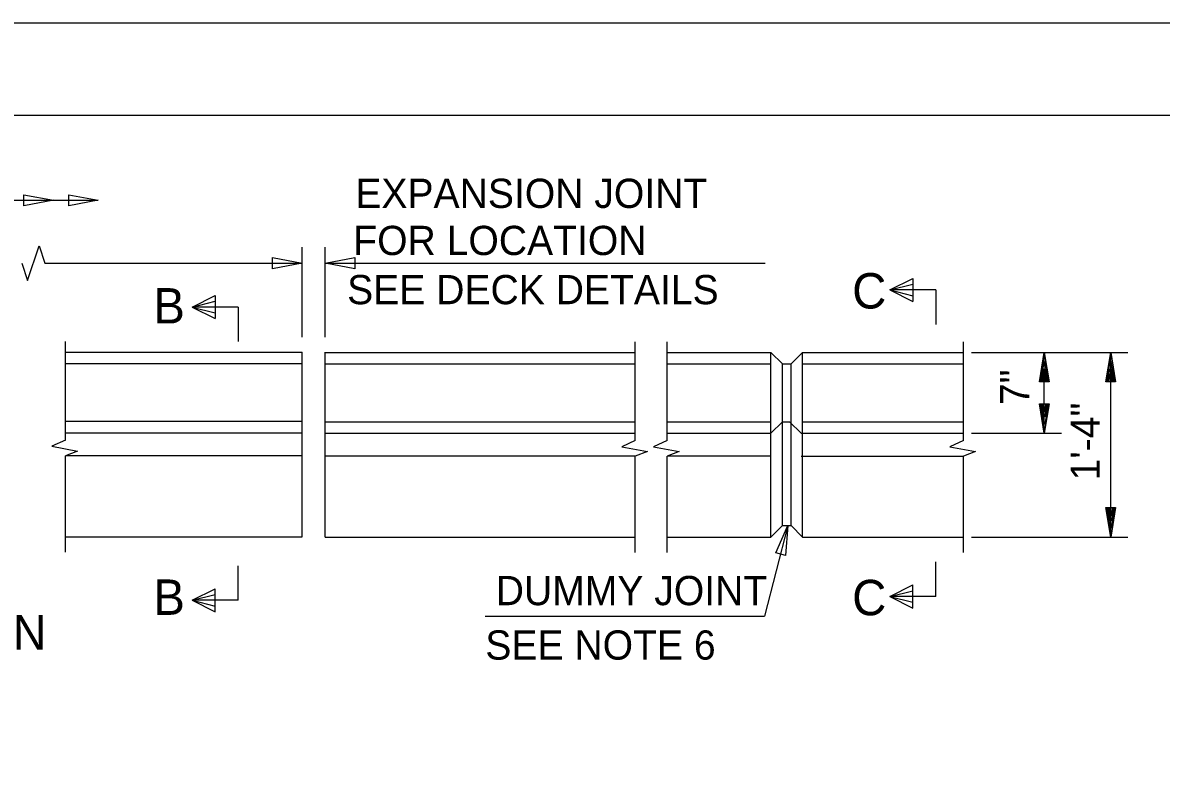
# Model space of a CAD drawing. Extents: x 0 to 34, y 0 to 23.5.
# Drawn here: x 9.78 to 15.94, y 17.93 to 22 of the extents above; entities that cross this region are included whole.
import ezdxf

# ---------------------------------------------------------------- set-up
doc = ezdxf.new("R2010")
doc.units = 0
for name, color, linetype in [('BORDER_ANNO_Cutsheet', 7, 'Continuous'), ('BRDG_ANNO_Anno-Sheet', 7, 'Continuous'), ('BRDG_ANNO_General-Notes', 7, 'Continuous'), ('BRDG_BASE_Obj-Line', 7, 'Continuous')]:
    doc.layers.add(name, color=color, linetype=linetype)

msp = doc.modelspace()

# ---------------------------------------------------------------- linework, layer by layer
at = {"layer": 'BORDER_ANNO_Cutsheet'}
msp.add_lwpolyline([(0, 22), (34, 22), (34, 0), (0, 0)], close=True, dxfattribs=at)
at = {"layer": 'BRDG_ANNO_Anno-Sheet'}
msp.add_lwpolyline([(1.5, 21.5), (33.5, 21.5), (33.5, 0.5), (1.5, 0.5)], close=True, dxfattribs=at)
at = {"layer": 'BRDG_ANNO_General-Notes'}
for p, q in [((2.9781, 21.0388), (10.1869, 21.0388)), ((9.7839, 21.0087), (9.7839, 21.0687)), ((9.7839, 21.0687), (9.9439, 21.0388)), ((9.9439, 21.0388), (9.7839, 21.0087)), ((10.0269, 21.0087), (10.0269, 21.0687)), ((10.0269, 21.0687), (10.1869, 21.0388)), ((10.1869, 21.0388), (10.0269, 21.0087)), ((11.2906, 20.2985), (11.2906, 20.7858)), ((11.4156, 20.2985), (11.4156, 20.7858)), ((11.1306, 20.6683), (11.1306, 20.7283)), ((11.1306, 20.7283), (11.2906, 20.6983)), ((11.4156, 20.6983), (11.5756, 20.7283)), ((11.5756, 20.7283), (11.5756, 20.6683)), ((9.8976, 20.6983), (11.2906, 20.6983)), ((11.2906, 20.6983), (11.1306, 20.6683)), ((11.4156, 20.6983), (13.798, 20.6983)), ((11.5756, 20.6683), (11.4156, 20.6983)), ((14.4728, 20.5532), (14.5978, 20.6157)), ((14.5978, 20.6157), (14.5978, 20.5532)), ((14.4728, 20.5532), (14.5978, 20.5844)), ((14.7228, 20.5532), (14.4728, 20.5532)), ((14.4728, 20.5532), (14.5978, 20.4907)), ((14.4728, 20.5532), (14.5978, 20.5219)), ((14.5978, 20.5532), (14.5978, 20.4907)), ((14.7228, 20.5532), (14.7228, 20.3657)), ((10.6951, 20.4609), (10.8201, 20.5234)), ((10.6951, 20.4609), (10.8201, 20.4921)), ((10.8201, 20.5234), (10.8201, 20.4609)), ((10.9451, 20.4609), (10.6951, 20.4609)), ((10.6951, 20.4609), (10.8201, 20.3984)), ((10.6951, 20.4609), (10.8201, 20.4296)), ((10.8201, 20.4609), (10.8201, 20.3984)), ((10.9451, 20.4609), (10.9451, 20.2734)), ((14.9156, 20.2151), (15.7633, 20.2151)), ((15.2889, 20.0595), (15.3065, 20.1665)), ((15.3098, 19.7776), (15.3098, 20.2151)), ((15.3307, 20.0595), (15.3131, 20.1665)), ((15.6486, 20.0595), (15.6662, 20.1665)), ((15.6696, 19.2151), (15.6696, 20.2151)), ((15.6905, 20.0595), (15.6729, 20.1665)), ((15.2948, 20.0595), (15.306, 20.1271)), ((15.3021, 20.0599), (15.3059, 20.0993)), ((15.3247, 20.0595), (15.3136, 20.1271)), ((15.3174, 20.0599), (15.3136, 20.0993)), ((15.6546, 20.0595), (15.6658, 20.1271)), ((15.6619, 20.0599), (15.6657, 20.0993)), ((15.6845, 20.0595), (15.6734, 20.1271)), ((15.6772, 20.0599), (15.6734, 20.0993)), ((15.2889, 19.9332), (15.3065, 19.8262)), ((15.2948, 19.9332), (15.306, 19.8656)), ((15.3021, 19.9328), (15.3059, 19.8934)), ((15.3307, 19.9332), (15.3131, 19.8262)), ((15.3247, 19.9332), (15.3136, 19.8656)), ((15.3174, 19.9328), (15.3136, 19.8934)), ((14.9156, 19.7776), (15.4035, 19.7776)), ((15.6486, 19.3707), (15.6662, 19.2637)), ((15.6546, 19.3707), (15.6658, 19.3031)), ((15.6619, 19.3703), (15.6657, 19.3309)), ((15.6905, 19.3707), (15.6729, 19.2637)), ((15.6845, 19.3707), (15.6734, 19.3031)), ((15.6772, 19.3703), (15.6734, 19.3309)), ((13.9222, 19.2776), (13.7952, 18.7874)), ((13.8563, 19.1294), (13.9222, 19.2776)), ((13.9222, 19.2776), (13.9079, 19.116)), ((14.9156, 19.2151), (15.7633, 19.2151)), ((13.9079, 19.116), (13.8563, 19.1294)), ((10.9451, 18.8728), (10.9451, 19.0603)), ((14.7228, 18.8935), (14.7228, 19.081)), ((10.6951, 18.8728), (10.8201, 18.9353)), ((10.8201, 18.8728), (10.8201, 18.9353)), ((14.4728, 18.8935), (14.5978, 18.956)), ((14.5978, 18.8935), (14.5978, 18.956)), ((10.6951, 18.8728), (10.8201, 18.9041)), ((10.9451, 18.8728), (10.6951, 18.8728)), ((10.6951, 18.8728), (10.8201, 18.8103)), ((10.6951, 18.8728), (10.8201, 18.8416)), ((10.8201, 18.8103), (10.8201, 18.8728)), ((14.4728, 18.8935), (14.5978, 18.9247)), ((14.7228, 18.8935), (14.4728, 18.8935)), ((14.4728, 18.8935), (14.5978, 18.831)), ((14.4728, 18.8935), (14.5978, 18.8622)), ((14.5978, 18.831), (14.5978, 18.8935)), ((12.2829, 18.7874), (13.7952, 18.7874))]:
    msp.add_line(p, q, dxfattribs=at)
msp.add_lwpolyline([(9.7726, 20.6983), (9.8039, 20.6046), (9.8664, 20.7921), (9.8976, 20.6983)], dxfattribs=at)
for points in [[(15.2834, 20.0551), (15.3098, 20.2151), (15.3362, 20.0551)], [(15.6432, 20.0551), (15.6696, 20.2151), (15.696, 20.0551)], [(15.3362, 19.9376), (15.3098, 19.7776), (15.2834, 19.9376)], [(15.696, 19.3751), (15.6696, 19.2151), (15.6432, 19.3751)]]:
    msp.add_lwpolyline(points, close=True, dxfattribs=at)
at = {"layer": 'BRDG_BASE_Obj-Line'}
for p, q in [((10.0093, 19.74), (10.0093, 20.2737)), ((13.0953, 19.738), (13.0953, 20.2718)), ((13.2671, 19.738), (13.2671, 20.2718)), ((14.8723, 19.738), (14.8723, 20.2718)), ((10.0093, 20.2171), (11.2906, 20.2171)), ((11.2906, 19.2171), (11.2906, 20.2171)), ((11.4156, 19.2151), (11.4156, 20.2171)), ((11.4156, 20.2151), (13.0953, 20.2151)), ((13.2671, 20.2151), (13.8296, 20.2151)), ((13.8296, 19.2151), (13.8296, 20.2151)), ((13.8921, 20.1526), (13.8296, 20.2151)), ((13.939, 20.1526), (14.0015, 20.2151)), ((14.0015, 20.2151), (14.8723, 20.2151)), ((14.0015, 19.2151), (14.0015, 20.2151)), ((10.0093, 20.1546), (11.2906, 20.1546)), ((11.4156, 20.1526), (13.0953, 20.1526)), ((13.2671, 20.1526), (13.8296, 20.1526)), ((13.8921, 19.2776), (13.8921, 20.1526)), ((13.8921, 20.1526), (13.939, 20.1526)), ((13.939, 19.2776), (13.939, 20.1526)), ((14.0015, 20.1526), (14.8723, 20.1526)), ((10.0093, 19.8421), (11.2906, 19.8421)), ((11.4156, 19.8401), (13.0953, 19.8401)), ((13.2671, 19.8401), (13.8296, 19.8401)), ((13.8296, 19.7776), (13.8921, 19.8401)), ((13.8921, 19.8401), (13.9312, 19.8401)), ((13.9937, 19.7776), (13.9312, 19.8401)), ((14.0015, 19.8401), (14.8723, 19.8401)), ((10.0093, 19.74), (9.9365, 19.7067)), ((10.0093, 19.7796), (11.2906, 19.7796)), ((11.4156, 19.7776), (13.0953, 19.7776)), ((13.0953, 19.738), (13.0224, 19.7047)), ((13.2671, 19.738), (13.1943, 19.7047)), ((13.2671, 19.7776), (13.8296, 19.7776)), ((13.9937, 19.7776), (14.8723, 19.7776)), ((14.8723, 19.738), (14.7995, 19.7047)), ((9.9365, 19.7067), (10.0745, 19.6808)), ((10.0745, 19.6808), (10.0093, 19.6546)), ((13.0224, 19.7047), (13.1605, 19.6789)), ((13.1605, 19.6789), (13.0953, 19.6526)), ((13.1943, 19.7047), (13.3323, 19.6789)), ((13.3323, 19.6789), (13.2671, 19.6526)), ((14.7995, 19.7047), (14.9375, 19.6789)), ((14.9375, 19.6789), (14.8723, 19.6526)), ((10.0093, 19.1342), (10.0093, 19.6546)), ((11.2906, 19.6546), (10.0093, 19.6546)), ((13.0953, 19.6526), (11.4156, 19.6526)), ((13.0953, 19.1322), (13.0953, 19.6526)), ((13.2671, 19.1322), (13.2671, 19.6526)), ((13.8296, 19.6526), (13.2671, 19.6526)), ((13.9937, 19.6526), (14.8723, 19.6526)), ((14.8723, 19.1322), (14.8723, 19.6526)), ((13.8296, 19.2151), (13.8921, 19.2776)), ((13.8921, 19.2776), (13.939, 19.2776)), ((14.0015, 19.2151), (13.939, 19.2776)), ((10.0093, 19.2171), (11.2906, 19.2171)), ((11.4156, 19.2151), (13.0953, 19.2151)), ((13.2671, 19.2151), (13.8296, 19.2151)), ((14.0015, 19.2151), (14.8723, 19.2151))]:
    msp.add_line(p, q, dxfattribs=at)

# ---------------------------------------------------------------- texts
at = {"layer": 'BRDG_ANNO_General-Notes'}
for s, height, p in [('EXPANSION JOINT', 0.158333, (11.5791, 20.9974)), ('FOR LOCATION', 0.158333, (11.568, 20.7423)), ('SEE DECK DETAILS', 0.158333, (11.5347, 20.4761)), ('C', 0.1917, (14.2697, 20.4529)), ('B', 0.1917, (10.4852, 20.3717)), ('DUMMY JOINT', 0.158333, (12.3395, 18.8465)), ('B', 0.1917, (10.4852, 18.7941)), ('C', 0.1917, (14.2697, 18.7919)), ('PARTIAL PARAPET PLAN', 0.1875, (6.8959, 18.605)), ('SEE NOTE 6', 0.15833, (12.2831, 18.5517))]:
    msp.add_text(s, height=height, dxfattribs=at).set_placement(p)
for s, p in [('7"', (15.2286, 19.9298)), ('1\'-4"', (15.6107, 19.5218))]:
    msp.add_text(s, height=0.15833, rotation=90, dxfattribs=at).set_placement(p)

doc.saveas('drawing.dxf')
